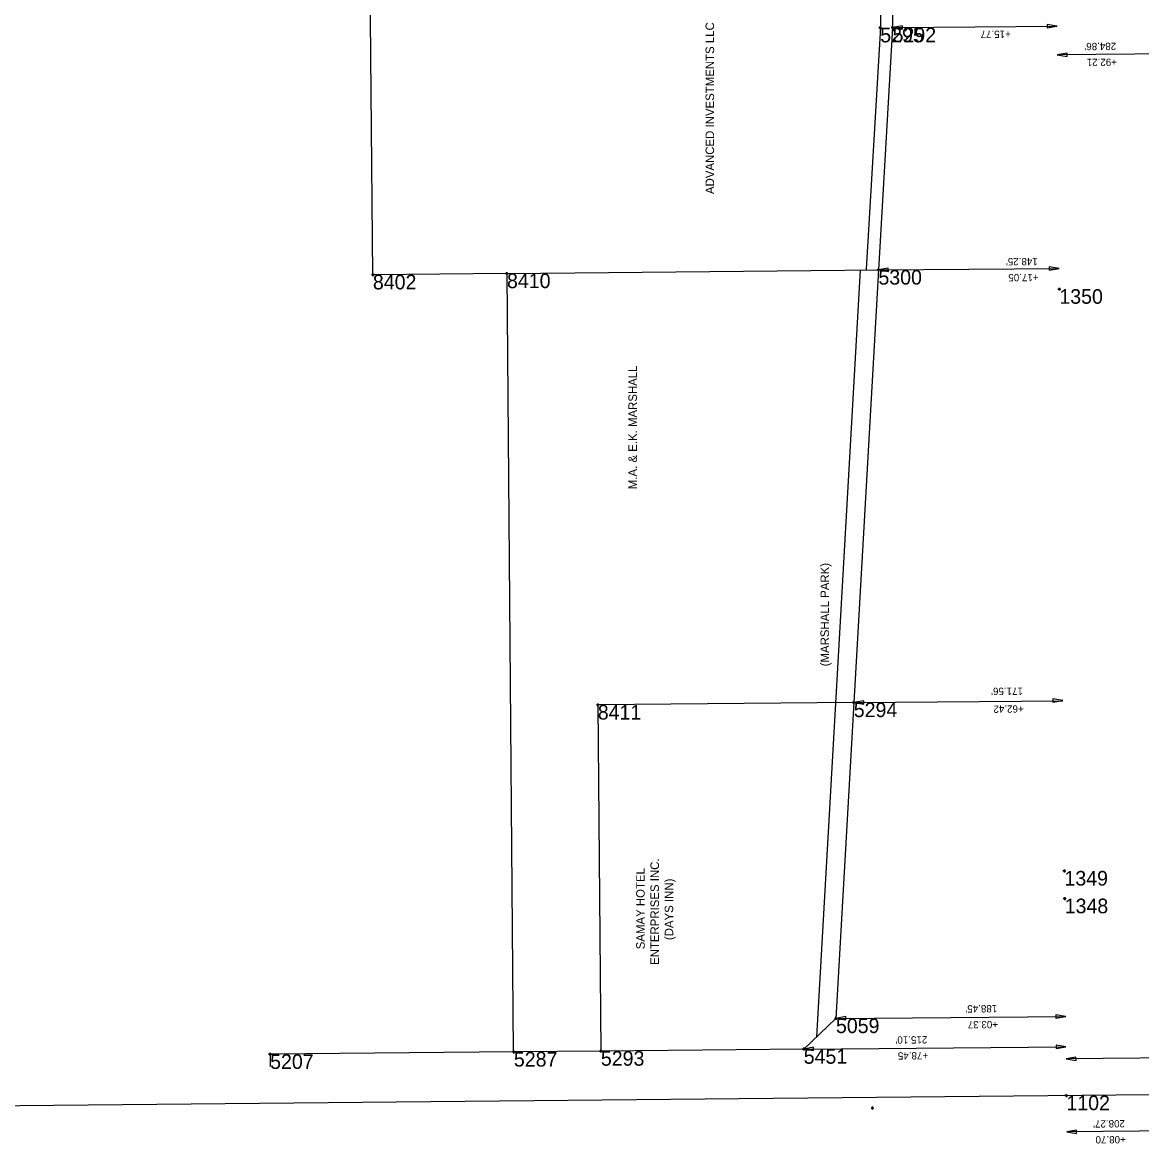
# Model space of a CAD drawing. Extents: x 2145146 to 2158053, y 137507 to 150829.
# Drawn here: x 2149992 to 2150909, y 140318 to 141238 of the extents above; entities that cross this region are included whole.
import ezdxf

# ---------------------------------------------------------------- set-up
doc = ezdxf.new("R2010")
doc.units = 0
for name, color, linetype in [('ALIGN_Cogo Points', 7, 'Continuous'), ('ALIGN_ROW Dimension', 7, 'Continuous'), ('ALIGN_ROW Line', 7, 'Continuous'), ('PLSS_Easement', 7, 'Continuous'), ('PLSS_Property Line', 7, 'Continuous'), ('PLSS_Section Line', 7, 'Continuous'), ('PLSS_Text_TURNED OFF', 7, 'Continuous')]:
    doc.layers.add(name, color=color, linetype=linetype)

# ---------------------------------------------------------------- blocks, each defined once
blk = doc.blocks.new('Arrowhd')
at = {"layer": 'PLSS_Property Line'}
blk.add_lwpolyline([(0.125, -0.021), (0.125, 0.021), (0, 0)], close=True, dxfattribs=at)

msp = doc.modelspace()

# ---------------------------------------------------------------- linework, layer by layer
at = {"layer": 'ALIGN_Cogo Points'}
for points in [[(2150695.12, 141233.77), (2150695.12, 141234.97), (2150695.12, 141233.77), (2150693.92, 141233.77), (2150695.12, 141233.77), (2150695.12, 141232.57), (2150695.12, 141233.77), (2150696.32, 141233.77)], [(2150705.24, 141233.86), (2150705.24, 141235.06), (2150705.24, 141233.86), (2150704.04, 141233.86), (2150705.24, 141233.86), (2150705.24, 141232.66), (2150705.24, 141233.86), (2150706.44, 141233.86)], [(2150279.02, 141031.11), (2150279.02, 141032.31), (2150279.02, 141031.11), (2150277.82, 141031.11), (2150279.02, 141031.11), (2150279.02, 141029.91), (2150279.02, 141031.11), (2150280.22, 141031.11)], [(2150389.01, 141032.15), (2150389.01, 141033.35), (2150389.01, 141032.15), (2150387.81, 141032.15), (2150389.01, 141032.15), (2150389.01, 141030.95), (2150389.01, 141032.15), (2150390.21, 141032.15)], [(2150693.6, 141035.03), (2150693.6, 141036.23), (2150693.6, 141035.03), (2150692.4, 141035.03), (2150693.6, 141035.03), (2150693.6, 141033.83), (2150693.6, 141035.03), (2150694.8, 141035.03)], [(2150841.99, 141019.29), (2150841.99, 141020.49), (2150841.99, 141019.29), (2150840.79, 141019.29), (2150841.99, 141019.29), (2150841.99, 141018.09), (2150841.99, 141019.29), (2150843.19, 141019.29)], [(2150673.39, 140680.22), (2150673.39, 140681.42), (2150673.39, 140680.22), (2150672.19, 140680.22), (2150673.39, 140680.22), (2150673.39, 140679.02), (2150673.39, 140680.22), (2150674.59, 140680.22)], [(2150463.48, 140678.23), (2150463.48, 140679.43), (2150463.48, 140678.23), (2150462.28, 140678.23), (2150463.48, 140678.23), (2150463.48, 140677.03), (2150463.48, 140678.23), (2150464.68, 140678.23)], [(2150846.17, 140542.04), (2150846.17, 140543.24), (2150846.17, 140542.04), (2150844.97, 140542.04), (2150846.17, 140542.04), (2150846.17, 140540.84), (2150846.17, 140542.04), (2150847.37, 140542.04)], [(2150846.37, 140519.31), (2150846.37, 140520.51), (2150846.37, 140519.31), (2150845.17, 140519.31), (2150846.37, 140519.31), (2150846.37, 140518.11), (2150846.37, 140519.31), (2150847.57, 140519.31)], [(2150658.77, 140421.03), (2150658.77, 140422.23), (2150658.77, 140421.03), (2150657.57, 140421.03), (2150658.77, 140421.03), (2150658.77, 140419.83), (2150658.77, 140421.03), (2150659.97, 140421.03)], [(2150465.99, 140394.26), (2150465.99, 140395.46), (2150465.99, 140394.26), (2150464.79, 140394.26), (2150465.99, 140394.26), (2150465.99, 140393.06), (2150465.99, 140394.26), (2150467.19, 140394.26)], [(2150632.34, 140395.87), (2150632.34, 140397.07), (2150632.34, 140395.87), (2150631.14, 140395.87), (2150632.34, 140395.87), (2150632.34, 140394.67), (2150632.34, 140395.87), (2150633.54, 140395.87)], [(2150194.75, 140391.64), (2150194.75, 140392.84), (2150194.75, 140391.64), (2150193.55, 140391.64), (2150194.75, 140391.64), (2150194.75, 140390.44), (2150194.75, 140391.64), (2150195.95, 140391.64)], [(2150394.65, 140393.58), (2150394.65, 140394.78), (2150394.65, 140393.58), (2150393.45, 140393.58), (2150394.65, 140393.58), (2150394.65, 140392.38), (2150394.65, 140393.58), (2150395.85, 140393.58)], [(2150847.78, 140357.77), (2150847.78, 140358.97), (2150847.78, 140357.77), (2150846.58, 140357.77), (2150847.78, 140357.77), (2150847.78, 140356.57), (2150847.78, 140357.77), (2150848.98, 140357.77)], [(2150688.76, 140347.54), (2150688.76, 140348.74), (2150688.76, 140347.54), (2150687.56, 140347.54), (2150688.76, 140347.54), (2150688.76, 140346.34), (2150688.76, 140347.54), (2150689.96, 140347.54)]]:
    msp.add_lwpolyline(points, dxfattribs=at)
at = {"layer": 'ALIGN_ROW Dimension'}
for points in [[(2150705.24, 141233.86), (2150840.1, 141235.04)], [(2151125.16, 141213.99), (2150840.31, 141211.49)], [(2150693.6, 141035.03), (2150841.84, 141036.33)], [(2150673.39, 140680.22), (2150844.95, 140681.72)], [(2150658.77, 140421.03), (2150847.21, 140422.68)], [(2150632.34, 140395.87), (2150847.43, 140397.76)], [(2151060.66, 140389.75), (2150847.52, 140387.88)], [(2151056.3, 140329.83), (2150848.04, 140328.01)]]:
    msp.add_lwpolyline(points, dxfattribs=at)
at = {"layer": 'ALIGN_ROW Line'}
msp.add_lwpolyline([(2150273.72, 141631.09), (2150686.6, 141634.62), (2150706.66, 141628.13), (2150707.62, 141518.13), (2150709.35, 141335.2), (2150704.35, 141335.15), (2150705.24, 141233.86), (2150693.6, 141035.03), (2150673.39, 140680.22), (2150658.77, 140421.03), (2150632.34, 140395.87), (2150465.99, 140394.26), (2150394.65, 140393.58), (2150194.75, 140391.64), (2150194.84, 140381.64)], dxfattribs=at)
at = {"layer": 'PLSS_Easement'}
for points in [[(2150696.63, 141631.37), (2150697.62, 141518.05), (2150699.26, 141345.1), (2150694.26, 141345.05), (2150695.24, 141234.11), (2150683.62, 141035.61), (2150683.58, 141034.94)], [(2150678.6, 141034.89), (2150642.89, 140405.91)]]:
    msp.add_lwpolyline(points, dxfattribs=at)
at = {"layer": 'PLSS_Property Line'}
for points in [[(2150389.01, 141032.16), (2150279.02, 141031.11), (2150276.37, 141331.1), (2150273.72, 141631.09)], [(2150394.33, 140393.55), (2150389.02, 141032.16), (2150693.6, 141035.03)], [(2150673.39, 140680.22), (2150463.47, 140678.23), (2150465.99, 140394.26)]]:
    msp.add_lwpolyline(points, dxfattribs=at)
at = {"layer": 'PLSS_Section Line'}
msp.add_lwpolyline([(2148302.81, 140333.27), (2150944.98, 140358.89)], dxfattribs=at)

# ---------------------------------------------------------------- block references
at = {"layer": 'ALIGN_ROW Dimension', "yscale": 65}
for p, xscale, rotation in [((2150705.26, 141233.87), 65.00000000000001, 0.7805293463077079), ((2150840.04, 141235.07), 65, 180), ((2150840.31, 141211.49), 65.00000000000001, 0.7805293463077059), ((2150693.62, 141035.04), 65.00000000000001, 0.7805293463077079), ((2150841.78, 141036.36), 65, 180), ((2150673.41, 140680.22), 65.00000000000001, 0.7805293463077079), ((2150844.89, 140681.74), 65, 180), ((2150658.79, 140421.04), 65.00000000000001, 0.7805293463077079), ((2150847.15, 140422.71), 65, 180), ((2150632.36, 140395.88), 65.00000000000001, 0.7805293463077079), ((2150847.37, 140397.78), 65, 180), ((2150847.52, 140387.88), 65.00000000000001, 0.7805293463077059), ((2150848.04, 140328.01), 65.00000000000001, 0.7805293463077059)]:
    msp.add_blockref('Arrowhd', p, dxfattribs=dict(at, xscale=xscale, rotation=rotation))

# ---------------------------------------------------------------- texts
at = {"layer": 'ALIGN_Cogo Points'}
for s, p in [('5295', (2150695.12, 141221.77)), ('5292', (2150705.24, 141221.86)), ('8402', (2150279.02, 141019.11)), ('8410', (2150389.01, 141020.15)), ('5300', (2150693.6, 141023.03)), ('1350', (2150841.99, 141007.29)), ('5294', (2150673.39, 140668.22)), ('8411', (2150463.48, 140666.23)), ('1349', (2150846.17, 140530.04)), ('1348', (2150846.37, 140507.31)), ('5059', (2150658.77, 140409.03)), ('5451', (2150632.34, 140383.87)), ('5207', (2150194.75, 140379.64)), ('5287', (2150394.65, 140381.58)), ('5293', (2150465.99, 140382.26)), ('1102', (2150847.78, 140345.77))]:
    msp.add_text(s, height=12, dxfattribs=at).set_placement(p)
at = {"layer": 'ALIGN_ROW Dimension'}
for s, p in [('+15.77', (2150802.13, 141231.46)), ("284.86'", (2150888.59, 141221.46)), ('+92.21', (2150889.23, 141208.41)), ("148.25'", (2150824.25, 141044.94)), ('+17.05', (2150824.9, 141031.89)), ("171.56'", (2150812.11, 140692.46)), ('+62.42', (2150812.72, 140677.89)), ("188.45'", (2150791.02, 140432.05)), ('+03.37', (2150791.66, 140419)), ("215.10'", (2150733.66, 140406.52)), ('+78.45', (2150734.31, 140393.47)), ("208.27'", (2150895.77, 140337.68)), ('+08.70', (2150896.41, 140324.63))]:
    msp.add_text(s, height=6, rotation=180.3718, dxfattribs=at).set_placement(p)
at = {"layer": 'PLSS_Text_TURNED OFF'}
for s, p in [('ADVANCED INVESTMENTS LLC', (2150558.85, 141097.31)), ('M.A. & E.K. MARSHALL', (2150495.6, 140855.21)), ('(MARSHALL PARK)', (2150653.12, 140709.9)), ('ENTERPRISES INC.', (2150513.65, 140464.93)), ('SAMAY HOTEL', (2150501.96, 140477.78)), ('(DAYS INN)', (2150525.34, 140485.3))]:
    msp.add_text(s, height=7, rotation=90, dxfattribs=at).set_placement(p)

doc.saveas('drawing.dxf')
